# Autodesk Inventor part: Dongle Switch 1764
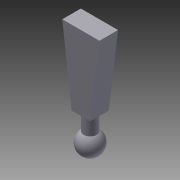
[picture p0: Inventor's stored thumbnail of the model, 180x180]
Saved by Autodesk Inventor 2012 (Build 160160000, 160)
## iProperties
Created: 2010-01
Part Number: Dongle Switch 1764
Document SubType Name: Modeling
Designer: jgehrig
Density: 1 g/cm^3
Material: Default
Author: jgehrig
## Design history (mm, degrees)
sketch "Sketch1"
  geometry: L1 (-6.921, 27.03)-(-1.841, 27.03); L2 (-3.111, 16.87)-(-5.651, 16.87); L3 (-6.921, 27.03)-(-5.651, 16.87); L4 (-3.111, 16.87)-(-1.841, 27.03); 1 further point
  constraints: 8 end point, 1 horizontal, 1 parallel
  dimensions: "d0" = 5.08 distance of L1.start L1.end; "d1" = 2.54 distance of L2.start L2.end; "d2" = 10.16 distance between parallel lines of L2 L1; "d3" = 1.27 horizontal distance of L1.start L2.end
extrude "Extrusion1" new body sketch "Sketch1" distance "d4" = 2.54; taper "d5" = 0 deg
workplane "Work Plane1"
sketch "Sketch2"
  geometry: L1 (-3.111, 16.87)-(-5.651, 16.87) reference; L2 (-4.381, 16.87)-(-4.381, 14.33); L3 (-3.492, 16.87)-(-3.492, 14.33); L4 (-4.381, 14.33)-(-3.492, 14.33); L5 (-4.381, 16.87)-(-3.492, 16.87); L6 (-4.381, 14.33)-(-4.381, 11.536); L7 (-4.381, 16.87)-(-3.492, 16.87); L8 (-3.492, 16.87)-(-4.381, 16.87); L9 (-4.381, 16.87)-(-3.492, 16.87); L10 (-3.492, 16.87)-(-3.492, 14.33); L11 (-3.492, 14.33)-(-4.381, 14.33); L12 (-4.381, 14.33)-(-4.381, 16.87); A1 r 1.587 centre (-4.381, 13.124) between (-4.381, 11.536) and (-4.381, 14.711); 1 further point
  constraints: 22 end point, 5 perpendicular, 3 parallel, 2 collinear, 2 point on circle, 2 point on line, 1 centre point, 1 horizontal, 1 midpoint
  dimensions: "d7" = 2.54 distance of L2.start L2.end; "d8" = 0.889 distance of L2.end L3.end; "d9" = 0 distance from line of L6 A1.centre; "d10" = 0.381 distance of A1.end L2.end; "d11" = 3.175 distance of L6.end A1.end
revolve "Revolution1" sketch "Sketch2" stored, may be unused: angle "d12" = 90 deg
body "Solid1"
other parameters: "d6" = 1.27
